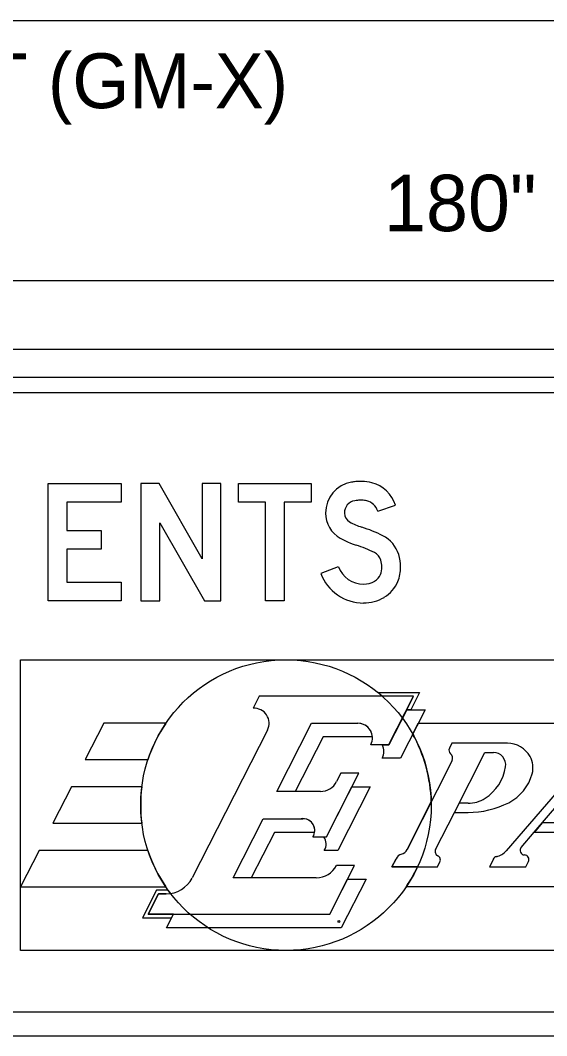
# Model space of a CAD drawing. Extents: x 10268259 to 10268554, y 2141099 to 2141249.
# Drawn here: x 10268362.08 to 10268368.8, y 2141190.57 to 2141203.53 of the extents above; entities that cross this region are included whole.
import ezdxf

# ---------------------------------------------------------------- set-up
doc = ezdxf.new("R2010")
doc.units = 0
for name, color, linetype in [('56', 7, 'Continuous'), ('60', 7, 'Continuous'), ('62', 7, 'Continuous'), ('Default', 7, 'Continuous'), ('GSColorFill', 7, 'Continuous'), ('GSDims', 7, 'Continuous'), ('GSSign', 7, 'Continuous'), ('Level 54', 7, 'Continuous')]:
    doc.layers.add(name, color=color, linetype=linetype)

msp = doc.modelspace()

# ---------------------------------------------------------------- linework, layer by layer
at = {"layer": '56'}
for p, q in [((10268365.236, 2141194.47), (10268364.274, 2141192.582)), ((10268369.468, 2141194.301), (10268368.283, 2141192.929)), ((10268367.593, 2141194.08), (10268367.019, 2141192.945)), ((10268367.593, 2141194.08), (10268367.593, 2141194.08)), ((10268381.427, 2141190.868), (10268354.48, 2141190.868)), ((10268381.427, 2141190.868), (10268354.48, 2141190.868)), ((10268381.427, 2141190.868), (10268354.48, 2141190.868)), ((10268354.48, 2141190.569), (10268381.427, 2141190.569)), ((10268354.48, 2141190.569), (10268381.427, 2141190.569)), ((10268354.48, 2141190.569), (10268381.427, 2141190.569))]:
    msp.add_line(p, q, dxfattribs=at)
for points in [[(10268363.366, 2141197.378), (10268362.676, 2141197.378), (10268362.676, 2141197.018), (10268363.113, 2141197.018), (10268363.113, 2141196.778), (10268362.676, 2141196.778), (10268362.676, 2141196.358), (10268363.366, 2141196.358), (10268363.366, 2141196.118), (10268362.436, 2141196.118), (10268362.436, 2141197.618), (10268363.366, 2141197.618)], [(10268363.366, 2141197.378), (10268362.676, 2141197.378), (10268362.676, 2141197.018), (10268363.113, 2141197.018), (10268363.113, 2141196.778), (10268362.676, 2141196.778), (10268362.676, 2141196.358), (10268363.366, 2141196.358), (10268363.366, 2141196.118), (10268362.436, 2141196.118), (10268362.436, 2141197.618), (10268363.366, 2141197.618)], [(10268363.366, 2141197.378), (10268362.676, 2141197.378), (10268362.676, 2141197.018), (10268363.113, 2141197.018), (10268363.113, 2141196.778), (10268362.676, 2141196.778), (10268362.676, 2141196.358), (10268363.366, 2141196.358), (10268363.366, 2141196.118), (10268362.436, 2141196.118), (10268362.436, 2141197.618), (10268363.366, 2141197.618)], [(10268364.641, 2141196.118), (10268364.641, 2141197.618), (10268364.401, 2141197.618), (10268364.401, 2141196.654), (10268363.851, 2141197.618), (10268363.621, 2141197.618), (10268363.621, 2141196.118), (10268363.861, 2141196.118), (10268363.861, 2141197.115), (10268364.431, 2141196.118)], [(10268364.641, 2141196.118), (10268364.641, 2141197.618), (10268364.401, 2141197.618), (10268364.401, 2141196.654), (10268363.851, 2141197.618), (10268363.621, 2141197.618), (10268363.621, 2141196.118), (10268363.861, 2141196.118), (10268363.861, 2141197.115), (10268364.431, 2141196.118)], [(10268364.641, 2141196.118), (10268364.641, 2141197.618), (10268364.401, 2141197.618), (10268364.401, 2141196.654), (10268363.851, 2141197.618), (10268363.621, 2141197.618), (10268363.621, 2141196.118), (10268363.861, 2141196.118), (10268363.861, 2141197.115), (10268364.431, 2141196.118)], [(10268365.796, 2141197.618), (10268365.796, 2141197.378), (10268365.451, 2141197.378), (10268365.451, 2141196.118), (10268365.211, 2141196.118), (10268365.211, 2141197.378), (10268364.866, 2141197.378), (10268364.866, 2141197.618)], [(10268365.796, 2141197.618), (10268365.796, 2141197.378), (10268365.451, 2141197.378), (10268365.451, 2141196.118), (10268365.211, 2141196.118), (10268365.211, 2141197.378), (10268364.866, 2141197.378), (10268364.866, 2141197.618)], [(10268365.796, 2141197.618), (10268365.796, 2141197.378), (10268365.451, 2141197.378), (10268365.451, 2141196.118), (10268365.211, 2141196.118), (10268365.211, 2141197.378), (10268364.866, 2141197.378), (10268364.866, 2141197.618)]]:
    msp.add_lwpolyline(points, close=True, dxfattribs=at)
for points in [[(10268366.644, 2141197.265), (10268366.871, 2141197.34)], [(10268366.644, 2141197.265), (10268366.871, 2141197.34)], [(10268366.644, 2141197.265), (10268366.871, 2141197.34)], [(10268366.141, 2141196.554), (10268365.916, 2141196.469)], [(10268366.141, 2141196.554), (10268365.916, 2141196.469)], [(10268366.141, 2141196.554), (10268365.916, 2141196.469)], [(10268367.103, 2141194.904), (10268365.132, 2141194.904), (10268365.053, 2141194.748)], [(10268366.555, 2141194.284), (10268366.787, 2141194.284), (10268366.787, 2141194.283), (10268367.015, 2141194.73), (10268366.787, 2141194.283), (10268366.701, 2141194.283), (10268366.787, 2141194.283), (10268366.787, 2141194.284), (10268367.103, 2141194.904)], [(10268365.912, 2141193.686), (10268365.357, 2141193.686), (10268365.8, 2141194.556), (10268366.391, 2141194.556)], [(10268368.301, 2141194.301), (10268367.591, 2141194.301), (10268367.56, 2141194.238)], [(10268367.383, 2141192.945), (10268367.623, 2141193.419), (10268367.623, 2141193.419), (10268368.01, 2141194.184), (10268368.122, 2141194.184)], [(10268365.816, 2141193.106), (10268365.99, 2141193.106), (10268366.404, 2141193.918), (10268366.172, 2141193.918), (10268366.118, 2141193.813)], [(10268368.475, 2141192.973), (10268368.643, 2141193.168), (10268369.273, 2141193.898), (10268369.194, 2141193.284), (10268368.745, 2141193.284), (10268368.644, 2141193.168), (10268369.182, 2141193.168), (10268369.155, 2141192.956)], [(10268367.797, 2141193.536), (10268367.683, 2141193.536), (10268367.624, 2141193.419), (10268367.797, 2141193.419)], [(10268365.86, 2141192.585), (10268364.796, 2141192.585), (10268365.18, 2141193.338), (10268365.689, 2141193.338)], [(10268363.943, 2141192.379), (10268363.846, 2141192.379), (10268363.714, 2141192.121), (10268363.714, 2141192.121), (10268366.033, 2141192.121), (10268366.349, 2141192.741), (10268366.117, 2141192.741)], [(10268366.878, 2141192.827), (10268366.826, 2141192.724), (10268367.406, 2141192.724), (10268367.437, 2141192.786)], [(10268368.121, 2141192.824), (10268368.07, 2141192.724), (10268368.534, 2141192.724), (10268368.568, 2141192.791)]]:
    msp.add_lwpolyline(points, dxfattribs=at)
msp.add_circle((10268365.472, 2141193.512), 1.855, dxfattribs=at)
for centre, radius, start, end in [((10268365.066, 2141194.557), 0.191, 332.9998, 93.8045), ((10268366.391, 2141194.37), 0.186, 332.2089, 90), ((10268365.912, 2141193.918), 0.232, 270, 332.9883), ((10268365.689, 2141193.188), 0.151, 327.421, 90), ((10268365.86, 2141192.875), 0.29, 270, 332.5096), ((10268363.943, 2141192.75), 0.371, 270, 332.9991)]:
    msp.add_arc(centre, radius, start, end, dxfattribs=at)
for centre, major_axis, ratio, start_param, end_param in [((10268366.422, 2141196.992), (0, 0.651), 0.999993, 0.090794, 0.175685), ((10268366.422, 2141196.992), (0, 0.651), 0.999993, 0.090794, 0.175685), ((10268366.422, 2141196.992), (0, 0.651), 0.999993, 0.090794, 0.175685), ((10268366.442, 2141196.772), (0, 0.872), 0.999993, 6.283185, 6.373979), ((10268366.442, 2141196.772), (0, 0.872), 0.999993, 6.283185, 6.373979), ((10268366.442, 2141196.772), (0, 0.872), 0.999993, 6.283185, 6.373979), ((10268366.442, 2141197.167), (0, 0.477), 0.999993, 6.012094, 6.283185), ((10268366.442, 2141197.167), (0, 0.477), 0.999993, 6.012094, 6.283185), ((10268366.442, 2141197.167), (0, 0.477), 0.999993, 6.012094, 6.283185), ((10268366.378, 2141197.24), (0, 0.4), 0.999993, 0.175685, 1.570796), ((10268366.378, 2141197.24), (0, 0.4), 0.999993, 0.175685, 1.570796), ((10268366.378, 2141197.24), (0, 0.4), 0.999993, 0.175685, 1.570796), ((10268366.452, 2141197.201), (0, 0.442), 0.999993, 5.034126, 6.012094), ((10268366.452, 2141197.201), (0, 0.442), 0.999993, 5.034126, 6.012094), ((10268366.452, 2141197.201), (0, 0.442), 0.999993, 5.034126, 6.012094), ((10268366.378, 2141197.24), (0, 0.16), 0.999993, 0.175685, 1.570796), ((10268366.378, 2141197.24), (0, 0.16), 0.999993, 0.175685, 1.570796), ((10268366.378, 2141197.24), (0, 0.16), 0.999993, 0.175685, 1.570796), ((10268366.422, 2141196.992), (0, 0.411), 0.999993, 0.090794, 0.175685), ((10268366.422, 2141196.992), (0, 0.411), 0.999993, 0.090794, 0.175685), ((10268366.422, 2141196.992), (0, 0.411), 0.999993, 0.090794, 0.175685), ((10268366.442, 2141196.772), (0, 0.632), 0.999993, 0, 0.090794), ((10268366.442, 2141196.772), (0, 0.632), 0.999993, 0, 0.090794), ((10268366.442, 2141196.772), (0, 0.632), 0.999993, 0, 0.090794), ((10268366.442, 2141197.167), (0, 0.237), 0.999993, 6.012094, 6.283185), ((10268366.442, 2141197.167), (0, 0.237), 0.999993, 6.012094, 6.283185), ((10268366.442, 2141197.167), (0, 0.237), 0.999993, 6.012094, 6.283185), ((10268366.452, 2141197.201), (0, 0.202), 0.999993, 5.034126, 6.012094), ((10268366.452, 2141197.201), (0, 0.202), 0.999993, 5.034126, 6.012094), ((10268366.452, 2141197.201), (0, 0.202), 0.999993, 5.034126, 6.012094), ((10268366.348, 2141197.24), (0, 0.37), 0.999993, 1.570796, 2.627164), ((10268366.348, 2141197.24), (0, 0.37), 0.999993, 1.570796, 2.627164), ((10268366.348, 2141197.24), (0, 0.37), 0.999993, 1.570796, 2.627164), ((10268366.348, 2141197.24), (0, 0.13), 0.999993, 1.570796, 2.627164), ((10268366.348, 2141197.24), (0, 0.13), 0.999993, 1.570796, 2.627164), ((10268366.348, 2141197.24), (0, 0.13), 0.999993, 1.570796, 2.627164), ((10268366.687, 2141197.839), (0, 0.818), 0.999993, 2.627164, 2.834816), ((10268366.687, 2141197.839), (0, 0.818), 0.999993, 2.627164, 2.834816), ((10268366.687, 2141197.839), (0, 0.818), 0.999993, 2.627164, 2.834816), ((10268365.878, 2141195.284), (0, 1.862), 0.999993, 5.820582, 5.976409), ((10268365.878, 2141195.284), (0, 1.862), 0.999993, 5.820582, 5.976409), ((10268365.878, 2141195.284), (0, 1.862), 0.999993, 5.820582, 5.976409), ((10268366.687, 2141197.839), (0, 1.058), 0.999993, 2.627164, 2.834816), ((10268366.687, 2141197.839), (0, 1.058), 0.999993, 2.627164, 2.834816), ((10268366.687, 2141197.839), (0, 1.058), 0.999993, 2.627164, 2.834816), ((10268366.53, 2141196.592), (0, 0.4), 0.999993, 5.010707, 5.820582), ((10268366.53, 2141196.592), (0, 0.4), 0.999993, 5.010707, 5.820582), ((10268366.53, 2141196.592), (0, 0.4), 0.999993, 5.010707, 5.820582), ((10268365.878, 2141195.284), (0, 1.622), 0.999993, 5.820582, 5.976409), ((10268365.878, 2141195.284), (0, 1.622), 0.999993, 5.820582, 5.976409), ((10268365.878, 2141195.284), (0, 1.622), 0.999993, 5.820582, 5.976409), ((10268366.53, 2141196.592), (0, 0.16), 0.999993, 5.010707, 5.820582), ((10268366.53, 2141196.592), (0, 0.16), 0.999993, 5.010707, 5.820582), ((10268366.53, 2141196.592), (0, 0.16), 0.999993, 5.010707, 5.820582), ((10268366.394, 2141196.55), (0, 0.303), 0.999993, 4.712389, 5.010707), ((10268366.394, 2141196.55), (0, 0.303), 0.999993, 4.712389, 5.010707), ((10268366.394, 2141196.55), (0, 0.303), 0.999993, 4.712389, 5.010707), ((10268366.394, 2141196.55), (0, 0.543), 0.999993, 4.712389, 5.010707), ((10268366.394, 2141196.55), (0, 0.543), 0.999993, 4.712389, 5.010707), ((10268366.394, 2141196.55), (0, 0.543), 0.999993, 4.712389, 5.010707), ((10268366.463, 2141196.675), (0, 0.344), 0.999993, 1.931277, 3.141593), ((10268366.463, 2141196.675), (0, 0.344), 0.999993, 1.931277, 3.141593), ((10268366.463, 2141196.675), (0, 0.344), 0.999993, 1.931277, 3.141593), ((10268366.441, 2141196.55), (0, 0.256), 0.999993, 4.331279, 4.712389), ((10268366.441, 2141196.55), (0, 0.256), 0.999993, 4.331279, 4.712389), ((10268366.441, 2141196.55), (0, 0.256), 0.999993, 4.331279, 4.712389), ((10268366.441, 2141196.55), (0, 0.496), 0.999993, 4.331279, 4.712389), ((10268366.441, 2141196.55), (0, 0.496), 0.999993, 4.331279, 4.712389), ((10268366.441, 2141196.55), (0, 0.496), 0.999993, 4.331279, 4.712389), ((10268366.463, 2141196.675), (0, 0.584), 0.999993, 1.931277, 3.141593), ((10268366.463, 2141196.675), (0, 0.584), 0.999993, 1.931277, 3.141593), ((10268366.463, 2141196.675), (0, 0.584), 0.999993, 1.931277, 3.141593), ((10268366.463, 2141196.613), (0, 0.281), 0.999993, 3.141593, 3.672524), ((10268366.463, 2141196.613), (0, 0.281), 0.999993, 3.141593, 3.672524), ((10268366.463, 2141196.613), (0, 0.281), 0.999993, 3.141593, 3.672524), ((10268366.517, 2141196.52), (0, 0.173), 0.999993, 3.672524, 4.331279), ((10268366.517, 2141196.52), (0, 0.173), 0.999993, 3.672524, 4.331279), ((10268366.517, 2141196.52), (0, 0.173), 0.999993, 3.672524, 4.331279), ((10268366.517, 2141196.52), (0, 0.413), 0.999993, 3.672524, 4.331279), ((10268366.517, 2141196.52), (0, 0.413), 0.999993, 3.672524, 4.331279), ((10268366.517, 2141196.52), (0, 0.413), 0.999993, 3.672524, 4.331279), ((10268366.463, 2141196.613), (0, 0.521), 0.999993, 3.141593, 3.672524), ((10268366.463, 2141196.613), (0, 0.521), 0.999993, 3.141593, 3.672524), ((10268366.463, 2141196.613), (0, 0.521), 0.999993, 3.141593, 3.672524), ((10268368.301, 2141193.968), (0, 0.333), 0.992614, 5.226065, 6.283185), ((10268367.611, 2141194.212), (0, -0.0584), 0.992614, 4.240773, 5.605302), ((10268367.531, 2141194.112), (0, -0.0701), 0.992614, 1.099604, 2.46371), ((10268368.122, 2141194.026), (0, -0.158), 0.992614, 1.415043, 3.141593), ((10268368.337, 2141193.988), (0, 0.292), 0.992614, 4.445482, 5.226065), ((10268367.704, 2141194.092), (0, -0.584), 0.992614, 0.565847, 1.415043), ((10268368.057, 2141194.065), (0, -0.584), 0.992614, 0.465011, 1.30389), ((10268367.797, 2141193.944), (0, -0.409), 0.992614, 0, 0.565847), ((10268367.797, 2141194.587), (0, -1.168), 0.992614, 0, 0.465011), ((10268366.981, 2141192.774), (0, -0.117), 0.992614, 3.428379, 4.240701), ((10268366.916, 2141192.998), (0, -0.117), 0.992614, 0.286787, 1.099486), ((10268367.435, 2141192.918), (0, 0.0584), 0.992614, 1.099355, 2.701477), ((10268367.386, 2141192.813), (0, 0.0584), 0.992614, 4.241567, 5.84307), ((10268368.172, 2141192.797), (0, -0.0584), 0.992614, 3.363532, 4.241567), ((10268368.109, 2141193.082), (0, -0.234), 0.992614, 0.22194, 0.855152), ((10268368.519, 2141192.935), (0, 0.0584), 0.992614, 0.854904, 3.118676), ((10268368.517, 2141192.818), (0, 0.0584), 0.992614, 4.240773, 6.260268)]:
    msp.add_ellipse(centre, major_axis=major_axis, ratio=ratio, start_param=start_param, end_param=end_param, dxfattribs=at)
at = {"layer": '60'}
msp.add_line((10268341.73, 2141203.528), (10268393.98, 2141203.528), dxfattribs=at)
at = {"layer": 'Default'}
for p, q in [((10268366.787, 2141194.283), (10268367.015, 2141194.73)), ((10268367.249, 2141194.73), (10268366.933, 2141194.11)), ((10268367.015, 2141194.73), (10268367.249, 2141194.73)), ((10268365.357, 2141193.686), (10268365.8, 2141194.556)), ((10268365.8, 2141194.556), (10268366.391, 2141194.556)), ((10268367.091, 2141194.42), (10268367.16, 2141194.556)), ((10268365.946, 2141194.382), (10268365.591, 2141193.686)), ((10268366.576, 2141194.382), (10268365.946, 2141194.382)), ((10268366.701, 2141194.283), (10268366.787, 2141194.283)), ((10268366.933, 2141194.11), (10268366.701, 2141194.11)), ((10268365.591, 2141193.686), (10268365.357, 2141193.686)), ((10268365.99, 2141193.106), (10268366.315, 2141193.744)), ((10268366.549, 2141193.744), (10268366.136, 2141192.932)), ((10268366.315, 2141193.744), (10268366.549, 2141193.744)), ((10268367.019, 2141192.945), (10268367.327, 2141193.554)), ((10268364.796, 2141192.585), (10268365.18, 2141193.338)), ((10268365.18, 2141193.338), (10268365.667, 2141193.337)), ((10268365.325, 2141193.164), (10268365.03, 2141192.585)), ((10268365.837, 2141193.162), (10268365.325, 2141193.164)), ((10268365.954, 2141193.106), (10268365.99, 2141193.106)), ((10268366.136, 2141192.932), (10268365.962, 2141192.932)), ((10268365.03, 2141192.585), (10268364.796, 2141192.585)), ((10268366.033, 2141192.121), (10268366.26, 2141192.567)), ((10268366.495, 2141192.567), (10268366.179, 2141191.947)), ((10268366.26, 2141192.567), (10268366.495, 2141192.567)), ((10268363.946, 2141191.947), (10268364.035, 2141192.121)), ((10268364.035, 2141192.121), (10268366.033, 2141192.121)), ((10268366.179, 2141191.947), (10268363.946, 2141191.947))]:
    msp.add_line(p, q, dxfattribs=at)
for points in [[(10268366.647, 2141194.949), (10268367.178, 2141194.949), (10268367.067, 2141194.73), (10268367.015, 2141194.73), (10268367.103, 2141194.904), (10268366.7, 2141194.904)], [(10268363.969, 2141192.426), (10268363.817, 2141192.426), (10268363.639, 2141192.074), (10268364.011, 2141192.074), (10268364.035, 2141192.121), (10268363.714, 2141192.121), (10268363.846, 2141192.379), (10268363.943, 2141192.379), (10268364, 2141192.384)]]:
    msp.add_lwpolyline(points, close=True, dxfattribs=at)
for points in [[(10268363.938, 2141194.556), (10268363.147, 2141194.556), (10268362.91, 2141194.092), (10268363.71, 2141194.092)], [(10268367.16, 2141194.556), (10268373.815, 2141194.556), (10268372.751, 2141192.469), (10268367.006, 2141192.469)], [(10268363.632, 2141193.744), (10268362.733, 2141193.744), (10268362.497, 2141193.28), (10268363.632, 2141193.28)], [(10268363.71, 2141192.932), (10268362.32, 2141192.932), (10268362.083, 2141192.469), (10268363.939, 2141192.469)], [(10268367.152, 2141192.724), (10268366.826, 2141192.724), (10268366.878, 2141192.827)]]:
    msp.add_lwpolyline(points, dxfattribs=at)
msp.add_circle((10268366.149, 2141192.026), 0.0116, dxfattribs=at)
for centre, radius, start, end in [((10268365.472, 2141193.512), 1.855, 145.7732, 161.7934), ((10268366.391, 2141194.37), 0.186, 3.5833, 90), ((10268365.472, 2141193.512), 1.855, 1.293, 29.2768), ((10268366.537, 2141194.196), 0.186, 332.2089, 27.9127), ((10268365.472, 2141193.512), 1.855, 172.8195, 187.1825), ((10268365.689, 2141193.188), 0.151, 350.3502, 98.3344), ((10268365.835, 2141193.014), 0.151, 327.421, 37.9799), ((10268365.472, 2141193.512), 1.855, 198.2127, 214.2338), ((10268365.472, 2141193.512), 1.855, 325.7662, 334.8478)]:
    msp.add_arc(centre, radius, start, end, dxfattribs=at)
for centre, start_param, end_param in [((10268366.981, 2141192.774), 3.428379, 4.240701), ((10268366.916, 2141192.998), 0.286787, 1.099486)]:
    msp.add_ellipse(centre, major_axis=(0, -0.117), ratio=0.992614, start_param=start_param, end_param=end_param, dxfattribs=at)
at = {"layer": 'GSColorFill'}
msp.add_line((10268379.649, 2141199.328), (10268356.249, 2141199.328), dxfattribs=at)
at = {"layer": 'GSDims'}
msp.add_line((10268354.449, 2141200.207), (10268381.261, 2141200.207), dxfattribs=at)
at = {"layer": 'GSSign'}
msp.add_lwpolyline([(10268362.083, 2141195.368), (10268373.815, 2141195.368), (10268373.815, 2141191.656), (10268362.083, 2141191.656)], close=True, dxfattribs=at)
at = {"layer": 'Level 54'}
for p, q in [((10268379.649, 2141198.968), (10268356.249, 2141198.968)), ((10268356.249, 2141198.78), (10268379.649, 2141198.78))]:
    msp.add_line(p, q, dxfattribs=at)

# ---------------------------------------------------------------- texts
at = {"layer": '62'}
msp.add_text('MOUNTING:  MULTI-POST GROUND MOUNT (GM-X)', height=0.7, dxfattribs=at).set_placement((10268342.516, 2141202.407))
at = {"layer": 'GSDims'}
msp.add_text('180"', height=0.72, dxfattribs=at).set_placement((10268366.725, 2141200.837))

doc.saveas('drawing.dxf')
